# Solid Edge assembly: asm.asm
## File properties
Author: Deepak Maini
Template: Normal.asm
Last saved by: MYPC
Revision: 5
Application: Solid Edge
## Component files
endplatemod.par
diskmod.par
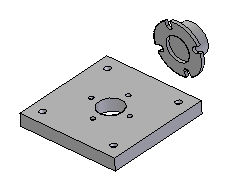
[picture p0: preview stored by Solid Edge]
